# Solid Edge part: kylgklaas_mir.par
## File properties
Author: Mac
Last saved by: Mac
Revision: 54
Accuracy: 0,990
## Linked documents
kylgklaas.par
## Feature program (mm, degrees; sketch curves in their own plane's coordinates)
part copy "CopiedPart_1"
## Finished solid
Body 1: solid body, 7 faces, 15 edges, 10 vertices.
  Faces by surface: plane 3, swept 2, offset 1, spline 1
  Edges by curve: intersection 10, line 5
Bounding box of the edges (mm; curved faces can reach further): 73.405 x 3.840 x 13.457, from (-22.4691, -30.0238, 3.4307) to (50.9356, -26.184, 16.8874).
Planar faces by outward normal: +z 1, -z 1, oblique 1
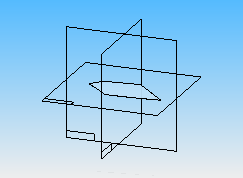
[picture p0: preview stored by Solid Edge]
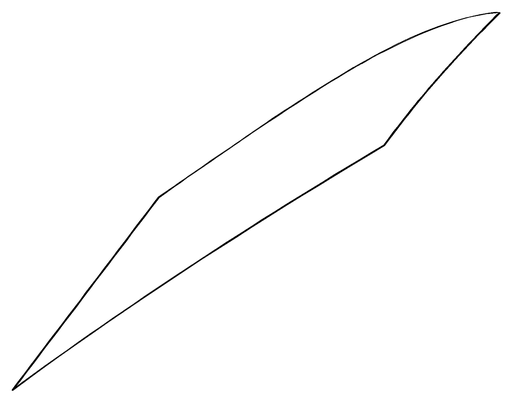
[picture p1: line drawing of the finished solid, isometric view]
